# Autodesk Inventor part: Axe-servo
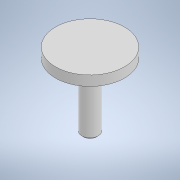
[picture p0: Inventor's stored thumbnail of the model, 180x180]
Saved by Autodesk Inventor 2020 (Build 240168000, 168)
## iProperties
Created: 2023-10
Part Number: Axe-servo
Material: Générique
Document SubType Name: Modeling
Designer: bruno
Density: 1 g/cm^3
Appearance: Par défaut
Author: bruno
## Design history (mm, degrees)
sketch "Esquisse1"
  geometry: L1 (0, 0)-(-3, 0); L2 (-3, 0)-(-3, 10.5); L3 (-3, 10.5)-(0, 10.5); L4 (0, 10.5)-(0, 0); L5 (-3, 5.759)-(-4.243, 5.759); L6 (-4.743, 5.259)-(-4.743, 0); L7 (-4.743, 0)-(-3, 0); L8 (-3, 0)-(-3, 5.759); L9 (-4.743, 0)-(-22.743, 0); L10 (-22.743, 0)-(-22.743, 2); L11 (-22.243, 2.5)-(-4.743, 2.5); L12 (-4.743, 2.5)-(-4.743, 0); L13 (-22.243, 2.5)-(-22.743, 2); L14 (-4.243, 5.759)-(-4.743, 5.259); 4 further points
  constraints: 28 end point, 6 parallel, 5 point on line, 3 horizontal, 3 perpendicular
  dimensions: "d0" = 3 distance of L2.end L3.end; "d1" = 10.5 distance of L1.end L2.end; "d2" = 18 distance of point (-22.743, 2.5) L11.end; "d3" = 2.5 distance of L9.end point (-22.743, 2.5); "d4" = 0.5 distance of L11.start point (-22.743, 2.5); "d5" = 0.5 distance of L10.end point (-22.743, 2.5) (= d4); "d6" = 0.5 distance of L5.end point (-4.743, 5.759) (= d4); "d7" = 0.5 distance of L6.start point (-4.743, 5.759) (= d6)
revolve "Révolution1" sketch "Esquisse1" stored, may be unused: angle "d8" = 90 deg
node "Solide1"
